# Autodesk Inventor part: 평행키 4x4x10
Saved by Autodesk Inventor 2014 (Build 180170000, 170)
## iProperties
Created: 2026-03
Part Number: 평행키 4x4x10
Material: 일반
Document SubType Name: Modeling
Designer: dg
Density: 1 g/cm^3
Appearance: 기본값
Author: dg
Author: jhkim
Description: 키 및 해당 키홈
Creation Date: 2025-06-27
Sending System: Autodesk Inventor 2026
Preprocessor: ST-DEVELOPER v20.1
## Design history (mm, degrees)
node "평행키 4x4x101"
body "Solid1"
node "기준1"
